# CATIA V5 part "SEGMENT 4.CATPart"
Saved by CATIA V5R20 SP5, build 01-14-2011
Part number: SEGMENT 4
Bounding box of the stored display mesh (mm): x 0 to 7, y -2.529 to 59.825, z -30.423 to 59.217
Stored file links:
  U:\IAO\Nouveau dossier\SEGMENT 4.CATPart
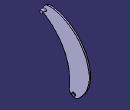
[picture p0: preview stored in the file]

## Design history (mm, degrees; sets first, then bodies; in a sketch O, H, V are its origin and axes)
Body1 (main body)
  Sketch1 on yz-plane, origin (0, 0, 0), H (0, 1, 0), V (0, 0, 1)
    arc A1 centre (0, 0) radius 60 from (59.1687, -9.9529) to (11.3216, 58.9222) ccw
    line L1 (-5, 53.9314) -> (-5, 48.8308)
    point P2 (-5, -29.5804)
    line L2 (-5, -29.5804) -> (-5, -36.3137)
    arc A2 centre (13.4001, 10.1775) radius 50 from (-5, -36.3137) to (59.1687, -9.9529) ccw
    reference projected circle E1 centre (13.4001, 10.1775) radius 52.5 from edge of DatumCurve5
    arc A3 centre (-62.9907, 9.6252) radius 70 from (-5, -29.5804) to (-5, 48.8308) ccw
    arc A4 centre (7.878, 41) radius 18.25 from (11.3216, 58.9222) to (-5, 53.9314) ccw
    point P7 (7.878, 41)
    radius A1 = 60
    distance L1 V = 5
    radius A3 = 70
    radius A4 = 18.25
    distance H P7 = 41
    coincidence: L1 P2, L1 L2
    vertical: L1 V
    concentricity: A2 E1
    tangency: A4 A1
  Pad1: profile Sketch1, direction (1, 0, 0), length 2
  Sketch2 on end face of Pad1, origin (2, 0, 0), H (0, 1, 0), V (0, 0, 1)
    circle A1 centre (0, 52) radius 2
    point P1 (0, 52)
    radius A1 = 2
    distance P1 H = 52
    coincidence: P1 V
  Pad2: profile Sketch2, direction (1, 0, 0), length 5
  Sketch3 on yz-plane, origin (0, 0, 0), H (0, 1, 0), V (0, 0, 1)
    line L1 (8.4403, -13.908) -> (68.2732, -66.0224)
    point P2 (68.2732, -66.0224)
    line L2 (68.2732, -66.0224) -> (-23.9057, -66.0224)
    point P3 (68.2732, -66.0224)
    point P4 (-23.9057, -66.0224)
    line L3 (-23.9057, -66.0224) -> (-23.9057, -13.908)
    point P5 (-23.9057, -66.0224)
    line L4 (8.4403, -13.908) -> (-23.9057, -13.908)
    coincidence: P3 L1, P4 P5, P2 P3
    horizontal: L2 H, L4 H
    vertical: L3 V
  Pocket1: profile Sketch3, direction (1, 0, 0), length 4, deactivated
  Sketch4 on end face of Pad1, origin (2, 38.1117, -24.6584), H (0, 1, 0), V (0, 0, 1)
    point P1 (0.5362, -2.6781)
    reference projected circle E1 centre (0.5362, -2.6781) radius 2.5 from edge of DatumCurve4
    concentricity: P1 E1
  Hole1: placed by Sketch4, at (2, 38.6478, -27.3365) direction (-1, 0, 0), diameter 5, through (limit type 3)
  DatumCurve1 to DatumCurve5
  Fillet1: radius 40, on edge [face of Pad1 from Sketch1.A1 | face of Pad1 from Sketch1.A2]
  Sketch5 on end face of Pad1, origin (2, 0, 0), H (0, 1, 0), V (0, 0, 1)
    arc A1 centre (75.1692, 24.9468) radius 71.1245 from (4.0447, 24.9468) to (60.3355, -44.6137) ccw
    line L1 (60.3355, -44.6137) -> (-40.9828, -62.7116)
    point P3 (-40.9828, -62.7116)
    line L2 (-40.9828, -62.7116) -> (-49.0295, 11.3266)
    point P4 (-40.9828, -62.7116)
    line L3 (-49.0295, 11.3266) -> (4.0447, 24.9468)
    coincidence: P4 L1, P3 P4
  Pocket2: profile Sketch5, direction (-1, 0, 0), length 2
  Sketch6 on end face of Pad1, origin (2, 0, 0), H (0, 1, 0), V (0, 0, 1)
    circle A1 centre (-37.8342, -14.5169) radius 71.5692
  Pocket3: profile Sketch6, direction (-1, 0, 0), length 2
  Fillet2: radius 7, on edge [face of Pad1 from Sketch1.A2 | face of Pocket2 from Sketch5.A1]; edge [face of Pocket2 from Sketch5.A1 | face of Pocket3 from Sketch6.A1]; edge [face of Pocket3 from Sketch6.A1 | face of Pad1 from Sketch1.L1]; edge [face of Pad1 from Sketch1.L1 | face of Pad1 from Sketch1.A4]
